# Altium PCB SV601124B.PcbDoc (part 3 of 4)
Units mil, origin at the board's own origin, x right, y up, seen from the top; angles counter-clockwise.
Board outline 3733 x 2734 mil, 4 copper layers (Top Layer, Mid-Layer 1, Mid-Layer 2, Bottom Layer), stack 60.2 mil thick; 246 components, 169 nets, 780 pads, 426 vias.
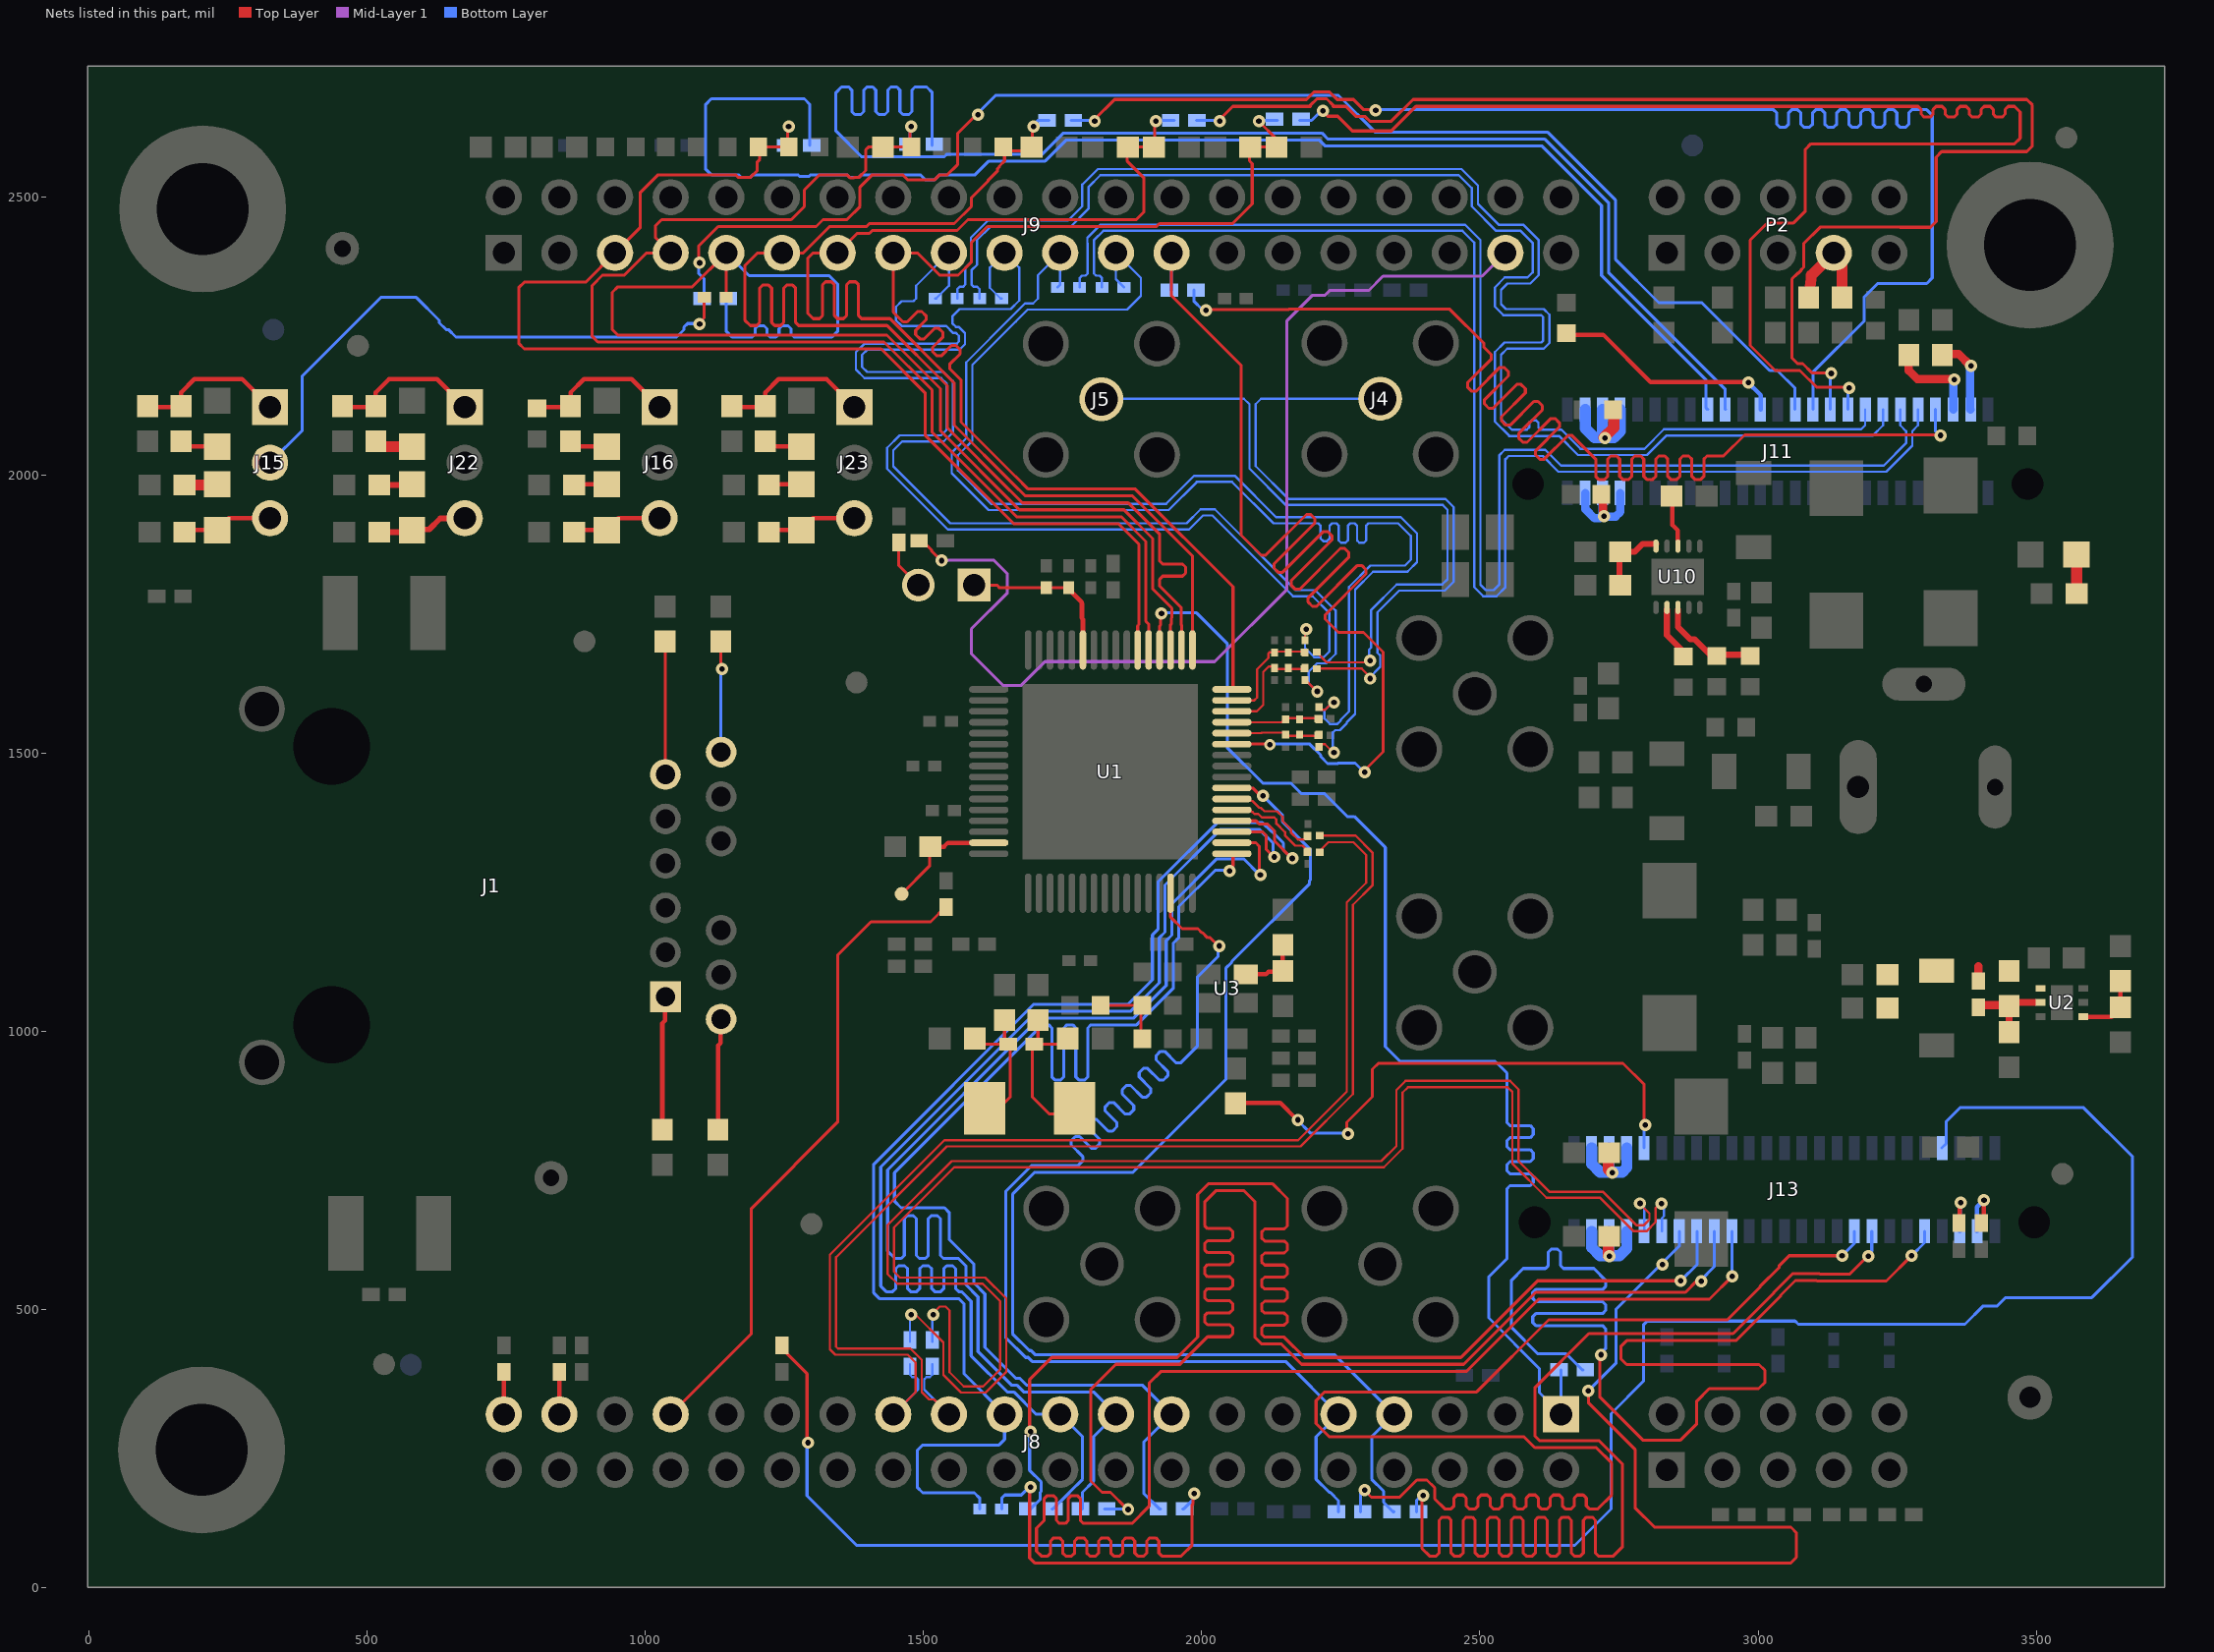
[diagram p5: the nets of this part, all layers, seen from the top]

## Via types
v1: diameter 22, hole 10, Top Layer to Bottom Layer, 385 vias
v2: diameter 19.68, hole 7.87, Top Layer to Bottom Layer, 40 vias
v3: diameter 20, hole 10, Top Layer to Bottom Layer, 1 vias

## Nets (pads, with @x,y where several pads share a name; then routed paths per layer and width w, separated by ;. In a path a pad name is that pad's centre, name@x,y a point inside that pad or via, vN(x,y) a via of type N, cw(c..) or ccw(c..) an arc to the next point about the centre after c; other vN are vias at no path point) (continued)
NetC5_1: C5.1 J4.1 | length 1252.1
  Top Layer w4.1: C5.1@2206,1652 2287.64,1652 2301,1638.64 v1@2301,1635
  Bottom Layer w4.1: v1@2301,1635 2321.05,1655.05 2321.05,1675.31 2316,1680.36 2316,1753 2355,1792 2437,1792 2453,1808 2453,1942 2438,1957 2156,1957 2097.1,2015.9 2097.1,2127.1 2107,2137 J4.1@2321,2137
  other v1: 2303,1634
NetC6_1: C6.1 J5.1 | length 1252.6
  Top Layer w4.1: C6.1@2206,1682 2224.9,1663.1 2297.1,1663.1 v1@2301,1667
  Bottom Layer w4.1: J5.1@1821,2137 2076,2137 2086,2127 2086,2011.3 2151.4,1945.9 2433.4,1945.9 2441.9,1937.4 2441.9,1812.6 2432.4,1803.1 2350.4,1803.1 2304.9,1757.6 2304.9,1689.96 2301,1686.06 v1@2301,1667
  other v1: 2303,1666
NetC7_1: C7.1 J1.7 | length 202.1
  Top Layer w8: C7.1@1131,822 1131,974.5 1136,979.5 J1.7@1136,1022
NetC8_1: C8.1 J1.1 | length 242.1
  Top Layer w8: C8.1@1031,822 1031,1014.5 1036,1019.5 J1.1@1036,1062
NetC9_1: C9.1 J1.6 | length 240
  Top Layer w5.4: J1.6@1036,1462 C9.1@1036,1702
NetC10_1: C10.1 J1.12 | length 200
  Top Layer w5.4: v1@1136,1652 C10.1@1136,1702
  Bottom Layer w5.4: J1.12@1136,1502 v1@1136,1652
  other v1: 1138,1651
NetC13_1: C13.1 C133.1 R86.2 R89.1 R90.2 U2.1 | length 30
  Top Layer w15: C13.1@3396,1087 3396,1117
NetC13_2: C13.2 R86.1 R87.2 U2.2 | length 154.1
  Top Layer w12: R87.2@3451,997 3451,1047 3456,1052 3498,1052
  Top Layer w15: C13.2@3396,1047 R86.1@3451,1047
NetC104_2: C104.2 U10.7 | length 93.5
  Top Layer w11: U10.7@2836.31,1757.94 2836.31,1727.94 2836,1727.63 2836,1712 2866,1682 C104.2@2866,1677
NetC273_1: C273.1 R652.1 R653.1 XTAL1.2 | length 272.7
  Top Layer w5.4: C273.1@1591,987 1601,977 R652.1@1656,977 ; XTAL1.2@1609,852 1626,852 1656,882 R652.1@1656,977 ; R653.1@1646,1022 1646,987 R652.1@1656,977
NetC274_1: C274.1 R652.2 R654.1 XTAL1.1 | length 300.7
  Top Layer w5.4: R654.1@1706,1022 1706,987 R652.2@1696,977 ; C274.1@1761,987 1751,977 R652.2@1696,977 ; XTAL1.1@1771,852 1726,852 1696,882 R652.2@1696,977
NetJ8_33: J8.33 R38.1 | length 1182.7
  Top Layer w5.4: J8.33@1046,312 1191,457 1191,682 1346,837 1346,1137 1406,1197 1513,1197 1541,1225 R38.1@1541,1227
NetJ8_37: J8.37 R77.2 | length 80
  Top Layer w8: J8.37@846,312 R77.2@846,392
NetJ8_39: J8.39 R73.2 | length 80
  Top Layer w8: J8.39@746,312 R73.2@746,392
NetJ11_3: J11.3 R62.1 | length 137.9
  Top Layer w15: R62.1@3331,2217 3361,2217 v1@3381,2197
  Bottom Layer w15: v1@3381,2197 3381,2118.13 J11.3@3381.55,2117.58
  other v1: 3383,2196
NetJ11_5: J11.5 R52.1 | length 170.2
  Top Layer w15: R52.1@3271,2217 3271,2187.5 3286.05,2172.45 v1@3350.55,2172.45
  Bottom Layer w15: J11.5@3350.55,2117.58 v1@3350.55,2172.45
  other v1: 3352.55,2171.45
NetJ11_27: J11.27 R63.1 | length 419.4
  Top Layer w8: R63.1@2656,2252 2721.72,2252 2806.72,2167 v1@2981,2167
  Bottom Layer w8: v1@2981,2167 3004.55,2143.45 J11.27@3004.55,2117.58
  other v1: 2983,2166
NetJ11_43: J11.43 J11.45 J11.47 R33.1 | length 256.8
  Top Layer w20: v1@2723,2067 2741,2085 R33.1@2741,2117
  Bottom Layer w20: J11.47@2689.55,2117.58 2689.55,2083.45 2706,2067 v1@2723,2067 ; J11.45@2720.55,2117.58 2720.55,2069.45 v1@2723,2067 ; J11.43@2752.55,2117.58 2752.55,2078.55 2741,2067 v1@2723,2067
  other v1: 2725,2066
NetJ11_44: J11.44 J11.46 J11.48 R23.2 | length 220.1
  Top Layer w15: v1@2721,1927 R23.2@2721,1967
  Bottom Layer w15: J11.48@2689.55,1967.58 2689.55,1938.45 2706,1922 2716,1922 v1@2721,1927 ; J11.46@2720.55,1967.58 2720.55,1927.45 v1@2721,1927 ; J11.44@2752.55,1967.58 2752.55,1933.55 2744.1,1925.1 2722.9,1925.1 v1@2721,1927
  other v1: 2723,1926
NetJ12_2: J12.2 R661.2 | length 94.5
  Top Layer w5.4: R661.2@1456,1882 1456,1837 J12.2@1491,1802
NetJ13_4: J13.4 R67.2 | length 108.5
  Top Layer w8: R67.2@3401,652 3406,657 v1(3406,697)
  Bottom Layer w8: J13.4@3393.36,640.8 3393.36,684.36 v1(3406,697)
NetJ13_6: J13.6 R69.2 | length 94.5
  Top Layer w8: R69.2@3361,652 3362.36,653.36 v1@3362.36,693.36
  Bottom Layer w8: J13.6@3362.36,640.8 v1@3362.36,693.36
  other v1: 3364.36,692.36
NetJ13_7: J13.7 R82.1 | length 3695.2
  Top Layer w5.4: R82.1@1246,432 1246,430 1291,385 v1@1291,262
  Bottom Layer w5.4: v1@1291,262 1291,165.62 1380.02,76.6 2670.68,76.6 2735.83,141.75 2735.83,313.04 2794.04,371.25 2794.04,472.5 2801.14,479.6 3066.58,479.6 3072.28,473.9 3371.74,473.9 3404.54,506.7 3430.14,506.7 3445.14,521.7 3599.78,521.7 3673,594.92 3673,775 3585,863 3363,863 3338,838 3338,798.44 J13.7@3330.36,790.8
  other v1: 1293,261
NetJ13_41: J13.41 R105.1 | length 979.2
  Top Layer w5.4: v1@2261,817 2261,836.7 2307,882.7 2307,932 2317.7,942.7 2757.3,942.7 2795.36,904.64 v1@2795.36,832.64
  Top Layer w8: R105.1@2061,872 2141,872 v1@2171,842
  Bottom Layer w5.4: v1@2171,842 2196,817 v1@2261,817 ; J13.41@2795.36,790.8 v1@2795.36,832.64
  other v1: 2263,816 2797.36,831.64 2173,841
NetJ13_43: J13.43 J13.45 J13.47 R58.1 | length 217.4
  Top Layer w20: R58.1@2731,782 2731,752 v1@2736,747
  Bottom Layer w20: J13.47@2701.36,790.8 2701.36,761.64 2716,747 2728.72,747 v1@2732.36,750.64 ; J13.45@2732.36,790.8 v1@2732.36,750.64 ; J13.43@2764.36,790.8 2764.36,755.36 2756,747 2736,747 v1@2732.36,750.64
  other v1: 2738,746
NetJ13_44: J13.44 J13.46 J13.48 R56.2 | length 213.6
  Top Layer w20: v1@2731,597 R56.2@2731,632
  Bottom Layer w20: J13.48@2701.36,640.8 2701.36,611.64 2716,597 v1@2731,597 ; J13.46@2732.36,640.8 2732.36,598.36 v1@2731,597 ; J13.44@2764.36,640.8 2764.36,610.36 2751,597 v1@2731,597
  other v1: 2733,596
NetJ15_1: J15.1 R25.2 R211.1 | length 276.7
  Top Layer w8: R25.2@106,2122 166,2122 166,2148 190,2172 276,2172 J15.1@326,2122
NetJ15_3: J15.3 LD21.2 R24.1 | length 165.4
  Top Layer w8: R24.1@171,1897 175.02,1901.02 231,1901.02 251.98,1922 J15.3@326,1922
NetJ16_1: J16.1 R16.2 R42.1 | length 276.7
  Top Layer w8: R16.2@806,2122 866,2122 866,2148 890,2172 976,2172 J16.1@1026,2122
NetJ16_3: J16.3 LD2.2 R15.1 | length 165.4
  Top Layer w8: R15.1@871,1897 875.02,1901.02 931,1901.02 951.98,1922 J16.3@1026,1922
NetJ22_1: J22.1 R18.2 R209.1 | length 276.7
  Top Layer w8: R18.2@456,2122 516,2122 516,2148 540,2172 626,2172 J22.1@676,2122
NetJ22_3: J22.3 LD20.2 R17.1 | length 156.8
  Top Layer w10: R17.1@522.5,1897 LD20.2@577.34,1897 ; LD20.2@582.34,1902 612,1902 632,1922 J22.3@676,1922
NetJ23_1: J23.1 R21.2 R210.1 | length 276.7
  Top Layer w8: R21.2@1156,2122 1216,2122 1216,2148 1240,2172 1326,2172 J23.1@1376,2122
NetJ23_3: J23.3 LD19.2 R19.1 | length 165.4
  Top Layer w8: R19.1@1221,1897 1225.02,1901.02 1281,1901.02 1301.98,1922 J23.3@1376,1922
NetLD2_1: LD2.1 R45.2 | length 60.4
  Top Layer w8: R45.2@871,1982 871.98,1982.98 LD2.1@931,1982.98
NetLD3_1: LD3.1 R42.2 | length 54
  Top Layer w8: R42.2@876.98,2051.02 LD3.1@931,2051.02
NetLD17_1: LD17.1 R170.1 | length 69.8
  Top Layer w20: R170.1@3572.5,1787 LD17.1@3572.5,1856.84
NetLD19_1: LD19.1 R212.2 | length 59
  Top Layer w8: R212.2@1221.98,1982.98 LD19.1@1281,1982.98
NetLD20_1: LD20.1 R213.2 | length 57.2
  Top Layer w10: R213.2@522.5,1982 LD20.1@579.66,1982
NetLD21_1: LD21.1 R214.1 | length 57.2
  Top Layer w20: R214.1@172.5,1982 LD21.1@229.66,1982
NetLD22_1: LD22.1 R209.2 | length 55.2
  Top Layer w20: R209.2@525.84,2050.66 LD22.1@581,2050.66
NetLD23_1: LD23.1 R210.2 | length 54
  Top Layer w8: R210.2@1226.98,2051.02 LD23.1@1281,2051.02
NetLD24_1: LD24.1 R211.2 | length 69.5
  Top Layer w8: R211.2@166,2062 176.98,2051.02 LD24.1@231,2051.02
NetP2_7: P2.7 R95.2 R96.2 | length 187.1
  Top Layer w20: R96.2@3091,2317 3096,2359 P2.7@3136,2399 3151,2384 R95.2@3151,2317
NetR9_1: R9.1 R20.2 U10.5 | length 131.5
  Top Layer w11: R20.2@2751,1802 2751,1862 2778.5,1862 2792.56,1876.06 U10.5@2816.63,1876.06
NetR43_2: R43.2 U10.3 | length 90.1
  Top Layer w8: R43.2@2846,1962 2846,1910.26 2856,1900.26 U10.3@2856,1876.06
NetR97_1: R97.1 R648.2 U3.1 | length 118.4
  Top Layer w8: U3.1@2079.5,1102.51 2115.51,1102.51 2120,1107 2146,1107 R97.1@2146,1157
NetR98_2: R98.2 R650.1 R660.2 | length 130
  Top Layer w5.4: R660.2@1821,1047 1891,1047 R98.2@1891,987
NetR133_2: R133.2 R177.2 U2.4 | length 118.9
  Top Layer w8: U2.4@3588.53,1026.4 3635.4,1026.4 3651,1042 R133.2@3651,1092
NetR640_1: R640.1 R641.2 U10.8 | length 181.5
  Top Layer w11: U10.8@2856,1757.94 2856,1727.23 2878.73,1704.5 2886.18,1704.5 2913.68,1677 2926,1677 R640.1@2986,1677
RBIAS: R645.2 TP1.1 U1.15 | length 213.1
  Top Layer w5.4: TP1.1@1461,1247 1511,1297 R645.2@1511,1332
  Top Layer w8: R645.2@1511,1332 1537,1332 1544.08,1339.08 U1.15@1615.46,1339.08
RESET_N: C318.2 J12.1 R35.1 U1.59 | length 323.8
  Top Layer w5.4: J12.1@1591,1802 1632.18,1802 1637.18,1797 1721,1797 C318.2@1761,1797 ; 1784.57,1771.43 1786.8,1769.2 1786.8,1740.78
  Top Layer w8: C318.2@1761,1797 1761,1795 1784.57,1771.43 1784.57,1743.01 1786.8,1740.78 U1.59@1786.8,1687.54
RESET_N_H: J9.37 R50.1 | length 1938.8
  Top Layer w5.4: R50.1@1496,1882 1498,1882 1514.86,1865.14 1514.86,1863.14 v1@1531,1847
  Mid-Layer 1 w5.4: v1@1531,1847 1626,1847 1651,1822 1651,1787.87 1586.5,1723.37 1586.5,1678.38 1642.89,1621.99 1675.99,1621.99 1718.5,1664.5 2023.5,1664.5 2153.5,1794.5 2153.5,2277.08 2198.92,2322.5 2221.21,2322.5 2230.31,2331.6 2300.6,2331.6 2326,2357 2504,2357 J9.37@2546,2399
  other v1: 1533,1846
RX_CLK: J9.25 R60.1 U1.43 | length 2320.5
  Top Layer w5.4: J9.25@1946,2399 1946,2322 2071,2197 2071,1892 2107.42,1855.58 2115.04,1855.58 2188.42,1928.96 2196.04,1928.96 2203.7,1921.3 2203.7,1913.68 2130.32,1840.3 2130.32,1832.68 2137.98,1825.02 2145.6,1825.02 2218.98,1898.4 2226.6,1898.4 2234.26,1890.74 2234.26,1883.12 2160.88,1809.74 2160.88,1802.12 2168.54,1794.46 2176.16,1794.46 2249.54,1867.84 2257.16,1867.84 2264.82,1860.18 2264.82,1852.56 2191.44,1779.18 2191.44,1771.56 2199.1,1763.9 2206.72,1763.9 2280.1,1837.28 2287.72,1837.28 2295.38,1829.62 2295.38,1822 2222,1748.62 2222,1741 2246,1717 2291,1717 2326.4,1681.6 2326.4,1502.4 v1@2291,1467 ; U1.43@2056.54,1516.2 v3@2121,1516.2
  Bottom Layer w5.4: R60.1@1946,2332 J9.25@1946,2399 ; v3@2121,1516.2 2194.53,1516.2 2214.15,1496.58 2214.15,1493.85 2226.64,1481.36 2244.58,1481.36 2245.22,1482 2276,1482 v1@2291,1467
  other v1: 2293,1466
  other v3: 2123,1515.2
RX_CLK_EMB: J11.7 R60.2 | length 2549.2
  Top Layer w5.4: v1@2006,2297 2024.68,2297 2024.98,2297.3 2156.3,2297.3 2156.7,2297.7 2446.15,2297.7 2507.51,2236.33 2507.51,2229.23 2520.73,2216.01 2520.73,2208.39 2477.98,2165.64 2477.98,2158.02 2485.64,2150.36 2493.26,2150.36 2536.01,2193.11 2543.63,2193.11 2551.29,2185.45 2551.29,2177.83 2508.54,2135.08 2508.54,2127.46 2516.2,2119.8 2523.82,2119.8 2566.57,2162.55 2574.19,2162.55 2581.85,2154.89 2581.85,2147.27 2539.1,2104.52 2539.1,2096.9 2546.76,2089.24 2554.38,2089.24 2597.13,2131.99 2604.75,2131.99 2612.41,2124.33 2612.41,2116.71 2569.66,2073.96 2569.66,2066.34 2577.32,2058.68 2584.94,2058.68 2627.69,2101.43 2635.31,2101.43 2642.97,2093.77 2642.97,2086.15 2600.22,2043.4 2600.22,2035.78 2607.88,2028.12 2615.5,2028.12 2658.25,2070.87 2665.87,2070.87 2708.24,2028.5 2708.24,1997.4 2713.64,1992 2724.44,1992 2729.84,1997.4 2729.84,2028.5 2735.24,2033.9 2746.04,2033.9 2751.44,2028.5 2751.44,1997.4 2756.84,1992 2767.64,1992 2773.04,1997.4 2773.04,2028.5 2778.44,2033.9 2789.24,2033.9 2794.64,2028.5 2794.64,1997.4 2800.04,1992 2810.84,1992 2816.24,1997.4 2816.24,2028.5 2821.64,2033.9 2832.44,2033.9 2837.84,2028.5 2837.84,1997.4 2843.24,1992 2854.04,1992 2859.44,1997.4 2859.44,2028.5 2864.84,2033.9 2875.64,2033.9 2881.04,2028.5 2881.04,1997.4 2886.44,1992 2897.24,1992 2902.64,1997.4 2902.64,2028.5 2908.04,2033.9 2937.9,2033.9 2976,2072 v1@3326,2072
  Bottom Layer w5.4: R60.2@1986,2332 1986,2312.3 2001.3,2297 v1@2006,2297 ; J11.7@3318.55,2117.58 3318.55,2079.45 v1@3326,2072
  other v1: 3328,2071 2008,2296
RX_DV: J9.7 R7.1 R8.2 R53.2 U1.53 | length 2336
  Top Layer w5.4: v1@1476,2627 1476,2589 1426,2589 1401.3,2589 1396.7,2584.4 1396.7,2546.95 1384.58,2534.83 1376.49,2534.83 1375.6,2533.94 1367.96,2533.94 1362.67,2539.23 1313.46,2539.23 1286.23,2512 1286.23,2482.33 1262.67,2458.77 1029.77,2458.77 1018.96,2447.96 1018.96,2426.04 J9.7@1046,2399 1002.9,2399 962.67,2358.77 923.31,2358.77 905,2340.46 905,2248.9 915,2238.9 1429.26,2238.9 1515.6,2152.56 1515.6,2076.86 1667.56,1924.9 1855.56,1924.9 1899.94,1880.52 1899.94,1736.94 1904.88,1732 U1.53@1904.88,1687.54
  Bottom Layer w5.4: R53.2@1476,2592 v1@1476,2627
  other v1: 1478,2626
RX_DV_EMB: J11.31 R53.1 | length 2538.8
  Bottom Layer w5.4: R53.1@1516,2592 1516,2687 1506,2697 1484.88,2697 1479.48,2691.6 1479.48,2653.1 1474.08,2647.7 1463.28,2647.7 1457.88,2653.1 1457.88,2691.6 1452.48,2697 1441.68,2697 1436.28,2691.6 1436.28,2653.1 1430.88,2647.7 1420.08,2647.7 1414.68,2653.1 1414.68,2691.6 1409.28,2697 1398.48,2697 1393.08,2691.6 1393.08,2653.1 1387.68,2647.7 1376.88,2647.7 1371.48,2653.1 1371.48,2691.6 1366.08,2697 1353,2697 1343,2687 1343,2617.81 1389.02,2571.79 1537.79,2571.79 1542.43,2576.43 1713.91,2576.43 1751.88,2614.4 2216.22,2614.4 2227.42,2603.2 2617.14,2603.2 2731.2,2489.14 2731.2,2363.62 2941,2153.82 2941,2118.13 J11.31@2941.55,2117.58
RX_ER: J9.5 R5.1 R6.2 R71.2 U1.54 | length 2320.4
  Top Layer w5.4: v1@1256,2627 1256,2589 1206,2589 1206,2567 1201.7,2562.7 1201.7,2546.95 1189.58,2534.83 1167.07,2534.83 1162.67,2539.23 1023.23,2539.23 991,2507 991,2444 J9.5@946,2399 893.37,2346.37 783,2346.37 773,2336.37 773,2236.5 783,2226.5 1424.12,2226.5 1503.2,2147.42 1503.2,2071.72 1662.42,1912.5 1850.42,1912.5 1887.54,1875.38 1887.54,1731.08 1885.2,1728.74 U1.54@1885.2,1687.54
  Bottom Layer w5.4: R71.2@1256,2592 v1@1256,2627
  other v1: 1258,2626
RX_ER_EMB: J11.33 R71.1 | length 2537.3
  Bottom Layer w5.4: R71.1@1296,2592 1296,2666 1286,2676 1119,2676 1109,2666 1109,2549.23 1119,2539.23 1168.02,2539.23 1172.42,2534.83 1189.58,2534.83 1193.98,2539.23 1274.49,2539.23 1277.42,2536.3 1294.58,2536.3 1297.51,2539.23 1363.02,2539.23 1367.42,2534.83 1384.58,2534.83 1388.98,2539.23 1494.49,2539.23 1503.33,2530.39 1520.49,2530.39 1529.33,2539.23 1593.15,2539.23 1617.95,2564.03 1719.05,2564.03 1757.02,2602 2211.08,2602 2222.28,2590.8 2612,2590.8 2718.8,2484 2718.8,2358.48 2906,2171.28 2906,2121.13 J11.33@2909.55,2117.58
RXD0: C1.2 R32.1 R34.2 R65.1 U1.44 | length 157.1
  Top Layer w4.1: U1.44@2056.54,1535.88 2107.32,1535.88 2108.18,1536.74 2145.56,1536.74 2151,1531.3 2176,1531.3 C1.2@2211,1531.3
RXD0_EMB: J11.9 R48.2 | length 2546
  Bottom Layer w4.1: R48.2@1821,2337 1821,2353.85 1816.9,2357.95 1810.65,2357.95 1806.55,2362.05 1806.55,2382.47 1806.42,2382.6 1806.42,2421.72 1823.28,2438.58 2468.72,2438.58 2489.9,2417.4 2489.9,1798.31 2506.21,1782 2529.64,1782 2545.95,1798.31 2545.95,2028 2551.85,2033.9 2613.12,2033.9 2641.17,2005.85 3230.55,2005.85 3277.1,2052.4 3277.1,2078.59 3287.55,2089.04 J11.9@3287.55,2117.58
RXD0_H: J9.23 R48.1 R65.2 | length 2161.6
  Top Layer w4.1: R65.2@2211,1512.7 2214.55,1516.25 2221.81,1516.25 v1@2236,1502.06
  Bottom Layer w4.1: R48.1@1861,2337 1846,2352 J9.23@1846,2399 1891,2354 1891,2322 1866.05,2297.05 1687.45,2297.05 1666.15,2275.75 1588.1,2197.71 1588.1,2061.41 1562.1,2035.41 1562.1,2007.9 1621.9,1948.1 1936.4,1948.1 1986.8,1998.5 2059.5,1998.5 2134,1924 2358,1924 2387.1,1894.9 2387.1,1843.08 2370.86,1826.84 2370.01,1826 2308,1826 2276,1794 2276,1570.36 2260.95,1555.31 2260.95,1553.6 2248.8,1541.45 2240.1,1541.45 2236,1537.35 v1@2236,1502.06
  other v1: 2238,1501.06
RXD1: C2.2 R30.1 R31.2 R64.1 U1.45 | length 157.7
  Top Layer w4.1: U1.45@2056.54,1555.56 2143.86,1555.56 2151,1562.7 2176,1562.7 2205.3,1562.7 2206,1562 C2.2@2211,1562
RXD1_EMB: J11.11 R70.1 | length 2547.8
  Bottom Layer w4.1: R70.1@1781,2337 1781,2353.85 1785.1,2357.95 1791.35,2357.95 1795.45,2362.05 1795.45,2377.87 1795.32,2378 1795.32,2416.28 1794.89,2416.7 1794.89,2425.9 1818.68,2449.68 2473.32,2449.68 2501,2422 2501,1802.91 2510.81,1793.1 2525.04,1793.1 2534.85,1802.91 2534.85,2035 2544.85,2045 2617.72,2045 2645.77,2016.95 3225.95,2016.95 3266,2057 3266,2078.59 3255.55,2089.04 J11.11@3255.55,2117.58
RXD1_H: J9.21 R64.2 R70.2 | length 2160.5
  Top Layer w4.1: R64.2@2211,1581.3 2214.55,1577.75 2221.81,1577.75 v1@2236,1591.94
  Bottom Layer w4.1: R70.2@1741,2337 1746,2342 J9.21@1746,2399 1706,2359 1706,2317 1697.15,2308.15 1682.85,2308.15 1661.55,2286.85 1577,2202.31 1577,2066.01 1551,2040.01 1551,2003.3 1617.3,1937 1941,1937 1991.4,1987.4 2054.9,1987.4 2129.4,1912.9 2209.64,1912.9 2213.74,1908.8 2213.74,1885.8 2218.54,1881 2225.34,1881 2230.14,1885.8 2230.14,1908.8 2234.24,1912.9 2242.44,1912.9 2246.54,1908.8 2246.54,1882.1 2250.64,1878 2258.84,1878 2262.94,1882.1 2262.94,1908.8 2267.04,1912.9 2275.24,1912.9 2279.34,1908.8 2279.34,1882.1 2283.44,1878 2291.64,1878 2295.74,1882.1 2295.74,1908.8 2299.84,1912.9 2353.4,1912.9 2376,1890.3 2376,1847.68 2365.42,1837.1 2303.4,1837.1 2264.9,1798.6 2264.9,1574.96 2249.85,1559.91 2249.85,1558.2 2244.2,1552.55 2230.45,1552.55 2221,1562 2221,1576.94 v1@2236,1591.94
  other v1: 2238,1590.94
RXD2: C5.2 R28.1 R29.2 R61.1 U1.46 | length 199.3
  Top Layer w4.1: U1.46@2056.54,1575.24 2099.24,1575.24 2110.95,1586.95 2110.95,1645.95 2120.9,1655.9 2126.4,1655.9 2131,1651.3 2156,1651.3 C5.2@2186,1651.3
RXD2_EMB: J11.13 R54.2 | length 2554.5
  Bottom Layer w4.1: R54.2@1601,2317 1601,2333.85 1596.9,2337.95 1590.65,2337.95 1586.55,2342.05 1586.55,2367.55 1596.68,2377.68 1596.68,2421.98 1620.6,2445.9 1764.58,2445.9 1796.68,2478 1796.68,2516.98 1818.28,2538.58 2462.4,2538.58 2485.58,2515.4 2485.58,2482.42 2529.42,2438.58 2573.32,2438.58 2594.9,2417 2594.9,2363.9 2586,2355 2545,2355 2527,2337 2527,2302.3 2542.4,2286.9 2610.4,2286.9 2613.9,2283.4 2613.9,2241.6 2610.4,2238.1 2544.5,2238.1 2527,2220.6 2527,2095.99 2552.99,2070 2642.3,2070 2676.45,2035.85 2800.55,2035.85 2835.6,2070.9 3206.41,2070.9 3224.55,2089.04 J11.13@3224.55,2117.58
RXD2_H: J9.19 R54.1 R61.2 | length 2154.9
  Top Layer w4.1: R61.2@2186,1632.7 2186,1632 v1@2206,1612
  Bottom Layer w4.1: R54.1@1641,2317 1639,2317 1619.42,2336.58 1619.42,2372.42 J9.19@1646,2399 1672.58,2372.42 1672.58,2313.58 1656.95,2297.95 1565.21,2297.95 1552.1,2284.84 1552.1,2272.4 1558.5,2266 1563.6,2266 1575,2254.6 1575,2235 1564.9,2224.9 1398.99,2224.9 1390.1,2216.01 1390.1,2193.9 1399,2185 1536.6,2185 1553.1,2168.5 1553.1,2076.5 1536.6,2060 1462,2060 1446.1,2044.1 1446.1,2015.6 1548.6,1913.1 1973.04,1913.1 1998.09,1938.15 2023.91,1938.15 2169.06,1793 2204,1793 2240.93,1756.07 2240.93,1678.58 2223.8,1661.45 2207.45,1661.45 2192.52,1646.52 2192.52,1625.48 v1@2206,1612
  other v1: 2208,1611
RXD3: C6.2 R26.1 R27.2 R51.1 U1.47 | length 199.6
  Top Layer w4.1: U1.47@2056.54,1594.92 2094.75,1594.92 2099.85,1600.02 2099.85,1650.85 2120,1671 2120,1679 2121.98,1680.98 R26.1@2131,1680.98 ; R26.1@2131,1682.7 C6.2@2186,1682.7
RXD3_EMB: J11.15 R47.2 | length 2560.5
  Bottom Layer w4.1: R47.2@1561,2317 1561,2333.85 1565.1,2337.95 1571.35,2337.95 1575.45,2342.05 1575.45,2372.15 1585.58,2382.28 1585.58,2426.58 1616,2457 1759.98,2457 1785.58,2482.6 1785.58,2521.58 1813.68,2549.68 2467,2549.68 2496.68,2520 2496.68,2487.02 2534.02,2449.68 2577.92,2449.68 2606,2421.6 2606,2359.3 2590.6,2343.9 2549.6,2343.9 2538.1,2332.4 2538.1,2306.9 2547,2298 2615,2298 2625,2288 2625,2237 2615,2227 2549.1,2227 2538.1,2216 2538.1,2100.59 2557.59,2081.1 2584.65,2081.1 2588.75,2085.2 2588.75,2093.9 2592.85,2098 2601.05,2098 2605.15,2093.9 2605.15,2085.2 2609.25,2081.1 2646.9,2081.1 2681.05,2046.95 2795.95,2046.95 2831,2082 3185.51,2082 3192.55,2089.04 J11.15@3192.55,2117.58
RXD3_H: J9.17 R47.1 R51.2 | length 2143.4
  Top Layer w4.1: R51.2@2186,1701.3 v1@2186,1723.8
  Bottom Layer w4.1: R47.1@1521,2317 1523,2317 1546,2340 J9.17@1546,2399 1487,2340 1487,2317 1482,2312 1461,2312 1451,2302 1451,2277.8 1461,2267.8 1541,2267.8 1553.9,2254.9 1559,2254.9 1563.9,2250 1563.9,2239.6 1560.3,2236 1394.4,2236 1392,2233.6 1379,2220.61 1379,2189.3 1394.4,2173.9 1532,2173.9 1542,2163.9 1542,2081.1 1532,2071.1 1457.4,2071.1 1435,2048.7 1435,2011 1544,1902 1977.64,1902 2002.69,1927.05 2019.31,1927.05 2164.46,1781.9 2199.4,1781.9 2229.83,1751.47 2229.83,1683.18 2219.2,1672.55 2202.45,1672.55 2186,1689 v1@2186,1723.8
  other v1: 2188,1722.8
RXD4: J9.15 R74.2 R290.1 R292.2 U1.48 | length 2322.8
  Top Layer w5.4: U1.48@2056.54,1614.6 2056.54,1799 1881.04,1974.5 1688.5,1974.5 1666.24,1996.76 1665.86,1996.76 1567.8,2094.82 1567.8,2170.52 1547.32,2191 1547.32,2198.62 1566.04,2217.34 1566.04,2224.96 1558.38,2232.62 1550.76,2232.62 1532.04,2213.9 1524.42,2213.9 1516.76,2221.56 1516.76,2229.18 1535.48,2247.9 1535.48,2255.52 1527.82,2263.18 1520.2,2263.18 1501.48,2244.46 1493.86,2244.46 1486.2,2252.12 1486.2,2259.74 1504.92,2278.46 1504.92,2286.08 1497.26,2293.74 1489.64,2293.74 1470.92,2275.02 1463.3,2275.02 1446,2292.32 J9.15@1446,2399 1489.1,2399 1529.33,2358.77 1562.67,2358.77 1586.23,2382.33 1586.23,2417.43 1615.17,2446.37 1918.93,2446.37 1924.19,2451.63 2055.63,2451.63 2091,2487 2091,2559.3 2086,2564.3 2086,2589 2136,2589 2136,2602 v1@2101,2637
  Bottom Layer w5.4: v1@2101,2637 R74.2@2136,2637
  other v1: 2103,2636
RXD4_EMB: J11.17 R74.1 | length 2552.4
  Top Layer w5.4: v1@2216,2655.3 2226.7,2644.6 2244.58,2644.6 2271.09,2618.09 2341.03,2618.09 2385.14,2662.2 3287.6,2662.2 3293,2656.8 3293,2648.4 3298.4,2643 3309.2,2643 3314.6,2648.4 3314.6,2656.8 3320,2662.2 3330.8,2662.2 3336.2,2656.8 3336.2,2648.4 3341.6,2643 3352.4,2643 3357.8,2648.4 3357.8,2656.8 3363.2,2662.2 3374,2662.2 3379.4,2656.8 3379.4,2648.4 3384.8,2643 3395.6,2643 3401,2648.4 3401,2656.8 3406.4,2662.2 3417.2,2662.2 3422.6,2656.8 3422.6,2648.4 3428,2643 3438.8,2643 3444.2,2648.4 3444.2,2656.8 3449.6,2662.2 3461,2662.2 3471,2652.2 3471,2605 3461,2595 3095,2595 3085,2585 3085,2474 3063.8,2452.8 3016.8,2452.8 2986,2422 2986,2232.72 3031.02,2187.7 3075.13,2187.7 3105.28,2157.55 v1@3161.55,2157.55
  Bottom Layer w5.4: R74.1@2176,2637 2197.7,2637 v1@2216,2655.3 ; J11.17@3161.55,2117.58 v1@3161.55,2157.55
  other v1: 3163.55,2156.55 2218,2654.3
RXD5: J9.13 R12.1 R13.2 R72.2 U1.49 | length 2322.1
  Top Layer w5.4: v1@1916,2637 1916,2589 1866,2589 1866,2564.3 1896,2534.3 1896,2472 1882.77,2458.77 1580.21,2458.77 1560.67,2439.23 1408.31,2439.23 1403.05,2433.97 1380.97,2433.97 J9.13@1346,2399 1302,2399 1292,2389 1292,2290.8 1302,2280.8 1313.4,2280.8 1318.8,2286.2 1318.8,2341.6 1324.2,2347 1335,2347 1340.4,2341.6 1340.4,2286.2 1345.8,2280.8 1356.6,2280.8 1362,2286.2 1362,2341.6 1367.4,2347 1378.2,2347 1383.6,2341.6 1383.6,2286.2 1389,2280.8 1439.98,2280.8 1555.4,2165.38 1555.4,2089.68 1660.72,1984.36 1661.1,1984.36 1683.36,1962.1 1875.9,1962.1 1983.6,1854.4 U1.49@1983.6,1687.54
  Bottom Layer w5.4: v1@1916,2637 R72.2@1951,2637
  other v1: 1918,2636
RXD5_EMB: J11.19 R72.1 | length 2543
  Top Layer w5.4: v1@2031,2637 2056.2,2662.2 2195.3,2662.2 2195.3,2663.88 2207.42,2676 2224.58,2676 2236.7,2663.88 2236.7,2662.2 2259.68,2662.2 2277.98,2643.9 2294.12,2643.9 2302.42,2635.6 2341,2635.6 2380,2674.6 3483,2674.6 3493,2664.6 3493,2591 3483,2581 3330,2581 3320,2571 3320,2455 3310,2445 3255.34,2445 3255.14,2445.2 3111.4,2445.2 3082.2,2416 3082.2,2373.07 3077.24,2368.11 3077.11,2367.09 3072.2,2362.17 3071,2362.17 3061,2352.17 3061,2210.1 3071,2200.1 3080.27,2200.1 3096.92,2183.45 v1@3129.55,2183.45
  Bottom Layer w5.4: R72.1@1991,2637 v1@2031,2637 ; J11.19@3129.55,2117.58 v1@3129.55,2183.45
  other v1: 3131.55,2182.45 2033,2636
RXD6: J9.11 R10.1 R11.2 R59.1 U1.50 | length 2325
  Top Layer w5.4: v1@1696,2627 1696,2589 1689,2582 1653,2582 1646,2589 1646,2564.3 1636.7,2555 1636.7,2553.42 1633.46,2550.18 1633.46,2546.59 1616.7,2529.83 1616.7,2528.42 1586.23,2497.95 1586.23,2482.33 1555.53,2451.63 1403.17,2451.63 1397.91,2446.37 1331.61,2446.37 1284.24,2399 J9.11@1246,2399 1202.23,2399 1179,2375.77 1179,2278.4 1189,2268.4 1200.4,2268.4 1205.8,2273.8 1205.8,2335.6 1211.2,2341 1222,2341 1227.4,2335.6 1227.4,2273.8 1232.8,2268.4 1243.6,2268.4 1249,2273.8 1249,2335.6 1254.4,2341 1265.2,2341 1270.6,2335.6 1270.6,2273.8 1276,2268.4 1434.84,2268.4 1543,2160.24 1543,2084.54 1655.58,1971.96 1655.96,1971.96 1678.22,1949.7 1868.3,1949.7 1924.74,1893.26 1924.74,1845.15 1930.14,1839.75 1965.8,1839.75 1971.2,1834.35 1971.2,1823.55 1965.8,1818.15 1930.14,1818.15 1924.74,1812.75 1924.74,1800.08 1963.6,1761.22 1963.6,1730.1 1963.92,1729.78 U1.50@1963.92,1687.54
  Bottom Layer w5.4: v1@1696,2627 1706,2637 R59.1@1726,2637
  other v1: 1698,2626
RXD6_EMB: J11.21 R59.2 | length 2554.5
  Top Layer w5.4: v1@1806,2637 1843.6,2674.6 2188.48,2674.6 2202.28,2688.4 2229.72,2688.4 2243.52,2674.6 2273,2674.6 2291.3,2656.3 v1@2311,2656.3
  Bottom Layer w5.4: R59.2@1766,2637 v1@1806,2637 ; v1@2311,2656.3 3028.03,2656.3 3033.43,2650.9 3033.43,2630.4 3038.83,2625 3049.63,2625 3055.03,2630.4 3055.03,2650.9 3060.43,2656.3 3071.23,2656.3 3076.63,2650.9 3076.63,2630.4 3082.03,2625 3092.83,2625 3098.23,2630.4 3098.23,2650.9 3103.63,2656.3 3114.43,2656.3 3119.83,2650.9 3119.83,2630.4 3125.23,2625 3136.03,2625 3141.43,2630.4 3141.43,2650.9 3146.83,2656.3 3157.63,2656.3 3163.03,2650.9 3163.03,2630.4 3168.43,2625 3179.23,2625 3184.63,2630.4 3184.63,2650.9 3190.03,2656.3 3200.83,2656.3 3206.23,2650.9 3206.23,2630.4 3211.63,2625 3222.43,2625 3227.83,2630.4 3227.83,2650.9 3233.23,2656.3 3244.03,2656.3 3249.43,2650.9 3249.43,2630.4 3254.83,2625 3265.63,2625 3271.03,2630.4 3271.03,2650.9 3276.43,2656.3 3303,2656.3 3313,2646.3 3313,2354 3303,2344 3215,2344 3191,2320 3191,2276.9 3098.55,2184.45 J11.21@3098.55,2117.58
  other v1: 1808,2636 2313,2655.3
RXD7: J9.9 R37.1 R49.1 U1.51 | length 2397.7
  Top Layer w5.4: R37.1@1146,2319 J9.9@1146,2399 1085,2338 951,2338 941,2328 941,2261.3 951,2251.3 1434.4,2251.3 1530.6,2155.1 1530.6,2079.4 1672.7,1937.3 1860.7,1937.3 1912.34,1885.66 1912.34,1794.94 1946.7,1760.58 1946.7,1743.42 1946,1742.72 1946,1732.72 1944.24,1730.96 U1.51@1944.24,1687.54
  Bottom Layer w5.4: R49.1@1146,2317 1146,2257.7 1156,2247.7 1192.13,2247.7 1197.53,2253.1 1197.53,2262.6 1202.93,2268 1213.73,2268 1219.13,2262.6 1219.13,2253.1 1224.53,2247.7 1235.33,2247.7 1240.73,2253.1 1240.73,2262.6 1246.13,2268 1256.93,2268 1262.33,2262.6 1262.33,2253.1 1267.73,2247.7 1336,2247.7 1346,2257.7 1346,2343 1331,2358 1187,2358 J9.9@1146,2399
RXD7_EMB: J11.23 R49.2 | length 2560.1
  Top Layer w5.4: v1@1096,2382.1 1096,2411 1131.37,2446.37 1307.37,2446.37 1319.77,2458.77 1362.67,2458.77 1386.23,2482.33 1386.23,2517.23 1408.23,2539.23 1462.67,2539.23 1471.51,2530.39 1520.49,2530.39 1529.33,2539.23 1543.23,2539.23 1561.3,2557.3 1561.3,2613.3 v1@1596,2648
  Bottom Layer w5.4: v1@1096,2382.1 1096,2362.4 1106,2352.4 R49.2@1106,2317 ; v1@1596,2648 1630,2682 2246,2682 2312.4,2615.6 2622.28,2615.6 2743.6,2494.28 2743.6,2387.72 2821.72,2309.6 2898.95,2309.6 3020.85,2187.7 3034.58,2187.7 3066.55,2155.73 J11.23@3066.55,2117.58
  other v1: 1098,2381.1 1598,2647
RXD7_LED: J15.2 R37.2 | length 1046.4
  Top Layer w5.4: v1@1096,2272 1106,2282 R37.2@1106,2319
  Bottom Layer w5.4: J15.2@326,2022 384,2080 384,2178 525,2319 589,2319 630.3,2277.7 630.3,2273.42 642.42,2261.3 646.7,2261.3 660.3,2247.7 1056.7,2247.7 1069.96,2260.96 1069.96,2265.66 1076.3,2272 v1@1096,2272
  other v1: 1098,2271
TX_CLK: J8.9 R80.1 U1.30 | length 2331.4
  Top Layer w5.4: U1.30@1944.24,1246.46 1944.24,1205.4 1965.04,1184.6 1993.4,1184.6 2000.3,1177.7 2001.58,1177.7 2010.78,1168.5 2015.59,1168.5 v1@2029.53,1154.56
  Bottom Layer w5.4: v1@2029.53,1154.56 2029.53,1134.53 1992.23,1097.23 1992.23,973.23 1962.19,943.19 1954.57,943.19 1933.69,964.07 1926.07,964.07 1918.41,956.41 1918.41,948.79 1939.29,927.91 1939.29,920.29 1931.63,912.63 1924.01,912.63 1903.13,933.51 1895.51,933.51 1887.85,925.85 1887.85,918.23 1908.73,897.35 1908.73,889.73 1901.07,882.07 1893.45,882.07 1872.57,902.95 1864.95,902.95 1857.29,895.29 1857.29,887.67 1878.17,866.79 1878.17,859.17 1870.51,851.51 1862.89,851.51 1842.01,872.39 1834.39,872.39 1826.73,864.73 1826.73,857.11 1847.61,836.23 1847.61,828.61 1839.95,820.95 1832.33,820.95 1811.45,841.83 1803.83,841.83 1796.17,834.17 1796.17,826.55 1817.05,805.67 1817.05,798.05 1809.39,790.39 1801.77,790.39 1780.89,811.27 1773.27,811.27 1765.61,803.61 1765.61,795.99 1786.49,775.11 1786.49,767.49 1778.4,759.4 1695.01,759.4 1647.9,712.29 1647.9,450.1 1683.77,414.23 1688.37,414.23 1695.6,407 2151,407 J8.9@2246,312 2205.77,271.77 2205.77,195.33 2229.33,171.77 2231.23,171.77 2246,157 R80.1@2246,137
  other v1: 2031.53,1153.56
TX_CLK_EMB: J13.18 R80.2 | length 2542.6
  Top Layer w5.4: v1@2291,177 2304.94,163.06 2356.06,163.06 2387,194 2405,194 2419,180 2419,160 2437,142 2448.4,142 2453.8,147.4 2453.8,161.6 2459.2,167 2470,167 2475.4,161.6 2475.4,147.4 2480.8,142 2491.6,142 2497,147.4 2497,161.6 2502.4,167 2513.2,167 2518.6,161.6 2518.6,147.4 2524,142 2534.8,142 2540.2,147.4 2540.2,161.6 2545.6,167 2556.4,167 2561.8,161.6 2561.8,147.4 2567.2,142 2578,142 2583.4,147.4 2583.4,161.6 2588.8,167 2599.6,167 2605,161.6 2605,147.4 2610.4,142 2621.2,142 2626.6,147.4 2626.6,161.6 2632,167 2642.8,167 2648.2,161.6 2648.2,147.4 2653.6,142 2664.4,142 2669.8,147.4 2669.8,161.6 2675.2,167 2686,167 2691.4,161.6 2691.4,147.4 2696.8,142 2712,142 2737.23,167.23 2737.23,224.23 2709.23,252.23 2598.77,252.23 2579.23,271.77 2229.33,271.77 2205.77,295.33 2205.77,336.77 2221.23,352.23 2494.27,352.23 2623.74,481.7 2944.98,481.7 3003.3,540.02 3003.3,541.28 3038.32,576.3 3038.32,579.32 3056,597 v1(3151,597)
  Bottom Layer w5.4: R80.2@2286,137 2286,172 v1@2291,177 ; v1(3151,597) 3173.36,619.36 J13.18@3173.36,640.8
  other v1: 2293,176
TX_EN: J8.1 R79.1 U1.52 | length 2356.1
  Top Layer w5.4: U1.52@1924.56,1687.54 1924.56,1728.6 1926,1730.04 v1@1926,1752
  Bottom Layer w5.4: v1@1926,1752 1991,1752 2046,1697 2046,1510.01 2109.82,1446.19 2160.39,1446.19 2178.88,1427.7 2220.3,1427.7 2261.7,1386.3 2274.58,1386.3 2330.3,1330.58 2330.3,972.7 2356.7,946.3 2527.7,946.3 2548.66,925.34 2548.66,836.11 2554.06,830.71 2590.6,830.71 2596,825.31 2596,814.51 2590.6,809.11 2554.06,809.11 2548.66,803.71 2548.66,792.91 2554.06,787.51 2590.6,787.51 2596,782.11 2596,771.31 2590.6,765.91 2554.06,765.91 2548.66,760.51 2548.66,749.71 2554.06,744.31 2590.6,744.31 2596,738.91 2596,728.11 2590.6,722.71 2554.06,722.71 2548.66,717.31 2548.66,591.66 2516,559 2516,485.19 2607.05,394.14 2607.05,350.95 J8.1@2646,312 R79.1@2646,392
  other v1: 1928,1751
TX_EN_EMB: J13.10 R79.2 | length 2552.9
  Top Layer w5.4: v1@2716,420 2716,342.65 2792.86,265.8 2860.8,265.8 2889.8,294.8 2889.8,335.8 2912.2,358.2 2955.14,358.2 2955.34,358 3001,358 3012.19,369.19 3012.19,391 3001.89,401.3 2764,401.3 2754,411.3 2754,434.5 2764,444.5 2960.4,444.5 3040.5,524.6 3040.5,525.86 3067.14,552.5 3104.86,552.5 3105.86,551.5 3230.5,551.5 v1(3276,597)
  Bottom Layer w5.4: R79.2@2686,392 2684,392 2655,421 2604,421 2557,468 2557,553 2578,574 2617.9,574 2623.3,579.4 2623.3,603.6 2628.7,609 2639.5,609 2644.9,603.6 2644.9,579.4 2650.3,574 2705,574 2726,553 2726,541.6 2720.6,536.2 2600.53,536.2 2595.13,530.8 2595.13,520 2600.53,514.6 2720.6,514.6 2726,509.2 2726,498.4 2720.6,493 2600.53,493 2595.13,487.6 2595.13,476.8 2600.53,471.4 2720.6,471.4 2726,466 2726,430 v1@2716,420 ; v1(3276,597) 3299.36,620.36 J13.10@3299.36,640.8
  other v1: 2718,419
TX_ER: J8.7 R84.1 U1.39 | length 2342
  Top Layer w5.4: U1.39@2056.54,1437.48 2091.92,1437.48 2105.73,1423.67 v1(2110.41,1423.67)
  Bottom Layer w5.4: v1(2110.41,1423.67) 2144.97,1389.11 2144.97,1377.63 2195.3,1327.3 2195.3,1272.08 2194.1,1270.88 2194.1,1265.56 2054.33,1125.79 2054.33,1124.25 2043.5,1113.42 2043.5,913.5 1877,747 1700.15,747 1660.3,707.15 1660.3,456.85 1690.52,426.63 1693.51,426.63 1700.74,419.4 2238.6,419.4 J8.7@2346,312 2305.77,271.77 2305.77,195.33 2327.14,173.96 2327.14,153.86 2344,137 R84.1@2346,137
TX_ER_EMB: J13.16 R84.2 | length 2547.2
  Top Layer w5.4: v1@2396,167 2396,71 2409.6,57.4 2421.49,57.4 2426.89,62.8 2426.89,121.6 2432.29,127 2443.09,127 2448.49,121.6 2448.49,62.8 2453.89,57.4 2464.69,57.4 2470.09,62.8 2470.09,121.6 2475.49,127 2486.29,127 2491.69,121.6 2491.69,62.8 2497.09,57.4 2507.89,57.4 2513.29,62.8 2513.29,121.6 2518.69,127 2529.49,127 2534.89,121.6 2534.89,62.8 2540.29,57.4 2551.09,57.4 2556.49,62.8 2556.49,121.6 2561.89,127 2572.69,127 2578.09,121.6 2578.09,62.8 2583.49,57.4 2594.29,57.4 2599.69,62.8 2599.69,121.6 2605.09,127 2615.89,127 2621.29,121.6 2621.29,62.8 2626.69,57.4 2637.49,57.4 2642.89,62.8 2642.89,121.6 2648.29,127 2659.09,127 2664.49,121.6 2664.49,62.8 2669.89,57.4 2680.69,57.4 2686.09,62.8 2686.09,121.6 2691.49,127 2702.29,127 2707.69,121.6 2707.69,62.8 2713.09,57.4 2740,57.4 2756,73.4 2756,223 2714.37,264.63 2607.37,264.63 2599.48,272.52 2599.48,360.52 2695.86,456.9 2955.26,456.9 3028.1,529.74 3028.1,531 3062,564.9 3110,564.9 3111,563.9 3164.72,563.9 3196,595.18 v1@3196,597
  Bottom Layer w5.4: R84.2@2386,137 2386,157 v1@2396,167 ; v1@3196,597 3204.36,605.36 J13.16@3204.36,640.8
  other v1: 2398,166 3198,596
TXD0: C3.2 R66.1 U1.38 | length 175.1
  Top Layer w4.1: U1.38@2056.54,1417.8 2083.61,1417.8 2087.35,1414.06 2091.65,1414.06 2103.76,1401.95 2106.63,1401.95 2113.03,1395.55 2127.97,1395.55 ; 2127.98,1395.54 2135.47,1395.54 2145.62,1385.39 2145.62,1377.9 2161,1362.52 2161,1357 2173,1345 2184,1345 C3.2@2191,1352
TXD0_EMB: J13.42 R101.2 | length 2562.2
  Top Layer w4.1: v1@1516,492 1529.48,505.48 1539.93,505.48 1547.1,498.31 1547.1,387.6 1572.6,362.1 1607.4,362.1 1637.9,392.6 1637.9,515.4 1606.7,546.6 1453.4,546.6 1436,564 1436,652 1551,767 2323,767 2350,794 2350,894.6 2366.5,911.1 2554.5,911.1 2569.6,896 2569.6,767.1 2624.7,712 2721,712 2781,652 2794.9,652 2804.9,662 2804.9,673.1 v1@2786,692
  Bottom Layer w4.1: R101.2@1516,442 v1@1516,492 ; v1@2786,692 2795.36,682.64 J13.42@2795.36,640.8
  other v1: 1518,491 2788,691
TXD0_H: J8.23 R66.2 R101.1 | length 2174.4
  Top Layer w4.1: J8.23@1546,312 1519.42,338.58 1510.52,338.58 1497.1,352 1497.1,409.9 1476.9,430.1 1346.6,430.1 1343.1,433.6 1343.1,594.15 1542.35,793.4 2178.1,793.4 2272.1,887.4 2272.1,1227.4 2307.1,1262.4 2307.1,1321.6 2276.7,1352 R66.2@2210.3,1352
  Bottom Layer w4.1: R101.1@1516,402 1516,383.15 1511.9,379.05 1505.65,379.05 1501.55,374.95 1501.55,356.45 J8.23@1546,312
TXD1: C4.2 R68.1 U1.37 | length 175.1
  Top Layer w4.1: U1.37@2056.54,1398.12 2087.22,1398.12 2090.96,1394.38 2091.65,1394.38 2095.18,1390.85 2102.03,1390.85 2108.43,1384.45 2123.37,1384.45 ; 2123.38,1384.44 2130.87,1384.44 2134.52,1380.79 2134.52,1373.3 2149.9,1357.92 2149.9,1352.4 2168.4,1333.9 2181.64,1333.9 2191,1324.54 C4.2@2191,1322
TXD1_EMB: J13.40 R102.2 | length 2578.3
  Top Layer w4.1: v1@1476,492 1485.29,492 1536,441.29 1536,383 1568,351 1612,351 1649,388 1649,520 1611.3,557.7 1458,557.7 1447.1,568.6 1447.1,647.4 1555.6,755.9 2327.6,755.9 2361.1,789.4 2361.1,890 2371.1,900 2549.9,900 2558.5,891.4 2558.5,762.5 2619.74,701.26 2620.62,700.9 2716.4,700.9 2776.4,640.9 2799.5,640.9 2816,657.4 2816,683.02 v1@2824.47,691.49
  Bottom Layer w4.1: R102.2@1476,442 v1@1476,492 ; v1@2824.47,691.49 2831,684.96 2831,668 2827.36,664.36 J13.40@2827.36,640.8
  other v1: 1478,491 2826.47,690.49
TXD1_H: J8.25 R68.2 R102.1 | length 2154.3
  Top Layer w4.1: J8.25@1446,312 1486,352 1486,405 1472,419 1342,419 1332,429 1332,598.75 1537.75,804.5 2173.5,804.5 2261,892 2261,1232 2296,1267 2296,1317 2272.95,1340.05 2227.85,1340.05 2210.3,1322.5 R68.2@2210.3,1322
  Bottom Layer w4.1: J8.25@1446,312 1490.45,356.45 1490.45,374.95 1486.35,379.05 1480.1,379.05 1476,383.15 R102.1@1476,402
TXD2: J8.21 R99.1 U1.36 | length 2323.4
  Top Layer w5.4: U1.36@2056.54,1378.44 2097.82,1378.44 2103.57,1372.69 2118.51,1372.69 2131,1360.2 2131,1342 v1@2161,1312
  Bottom Layer w5.4: R99.1@1601,142 1601,161.7 1591.7,171 1499,171 1489,181 1489,247 1499,257 1636,257 1646,267 J8.21@1646,312 1573.5,384.5 1573.5,510 1563.5,520 1421.03,520 1411.03,530 1411.03,761.41 1698.62,1049 1868,1049 1911.7,1092.7 1911.7,1173.42 1921.7,1183.42 1921.7,1268.42 2028.28,1375 2109.46,1375 2124.86,1359.6 2125.86,1359.6 2147.06,1338.4 2147.06,1325.94 v1@2161,1312
  other v1: 2163,1311
TXD2_EMB: J13.38 R99.2 | length 2543.9
  Top Layer w5.4: v1@1691,182 1691,54 1700,45 3059,45 3069,55 3069,99 3059,109 2814,109 2779,144 2779,249 2695,333 v1(2695,354)
  Bottom Layer w5.4: R99.2@1641,142 1641,161.7 1646.3,167 1676,167 v1@1691,182 ; v1(2695,354) 2744.44,403.44 2744.44,500.44 2826,582 2858.36,614.36 J13.38@2858.36,640.8
  other v1: 1693,181 2828,581
TXD3: J8.19 R83.1 U1.35 | length 2333.8
  Top Layer w5.4: U1.35@2056.54,1358.76 2109.24,1358.76 2116,1352 2116,1327 v1@2128.5,1314.5
  Bottom Layer w5.4: R83.1@1731,142 1733,142 1762.67,171.67 1762.67,171.77 1786.23,195.33 1786.23,271.77 J8.19@1746,312 1702.9,312 1662.67,352.23 1650.77,352.23 1585.9,417.1 1585.9,515.14 1568.64,532.4 1563.63,532.4 1558.23,537.8 1558.23,573.6 1552.83,579 1542.03,579 1536.63,573.6 1536.63,537.8 1531.23,532.4 1520.43,532.4 1515.03,537.8 1515.03,573.6 1509.63,579 1498.83,579 1493.43,573.6 1493.43,537.8 1488.03,532.4 1477.23,532.4 1471.83,537.8 1471.83,573.6 1466.43,579 1455.63,579 1450.23,573.6 1450.23,537.8 1444.83,532.4 1433.43,532.4 1423.43,542.4 1423.43,756.27 1703.76,1036.6 1873.14,1036.6 1924.1,1087.56 1924.1,1168.28 1934.1,1178.28 1934.1,1263.28 2033.42,1362.6 2104.32,1362.6 2128.5,1338.42 v1@2128.5,1314.5
  other v1: 2130.5,1313.5
TXD3_EMB: J13.36 R83.2 | length 2549.4
  Top Layer w5.4: v1@1691,282 1691,374.23 1731,414.23 1956.23,414.23 1993,451 1993,707 2012,726 2128,726 2154,700 2154,650.43 2148.6,645.03 2113.4,645.03 2108,639.63 2108,628.83 2113.4,623.43 2148.6,623.43 2154,618.03 2154,607.23 2148.6,601.83 2113.4,601.83 2108,596.43 2108,585.63 2113.4,580.23 2148.6,580.23 2154,574.83 2154,564.03 2148.6,558.63 2113.4,558.63 2108,553.23 2108,542.43 2113.4,537.03 2148.6,537.03 2154,531.63 2154,520.83 2148.6,515.43 2113.4,515.43 2108,510.03 2108,499.23 2113.4,493.83 2148.6,493.83 2154,488.43 2154,477.63 2148.6,472.23 2113.4,472.23 2108,466.83 2108,456.03 2113.4,450.63 2148.6,450.63 2185,414.23 2466,414.23 2603.77,552 v1(2861,552)
  Bottom Layer w5.4: R83.2@1691,142 1693,142 1709.86,158.86 1709.86,171.58 1711.7,173.42 1711.7,190.58 1691,211.28 v1@1691,282 ; v1(2861,552) 2890.36,581.36 J13.36@2890.36,640.8
  other v1: 1693,281
TXD4: J8.17 R76.1 U1.34 | length 2324.3
  Top Layer w5.4: U1.34@2056.54,1339.08 2097.6,1339.08 2103.6,1333.08 v1@2103.6,1282
  Bottom Layer w5.4: 1700.76,352.22 1680.22,352.22 1667.81,364.63 1658.37,364.63 1598.3,424.7 1598.3,523 1577,544.3 1577,578 1563,592 1536,592 1530.6,597.4 1530.6,663.6 1525.2,669 1514.4,669 1509,663.6 1509,597.4 1503.6,592 1492.8,592 1487.4,597.4 1487.4,663.6 1482,669 1471.2,669 1465.8,663.6 1465.8,597.4 1460.4,592 1449,592 1435.83,605.17 1435.83,751.13 1708.9,1024.2 1878.28,1024.2 1936.5,1082.42 1936.5,1163.14 1946.5,1173.14 1946.5,1229.32 2027.34,1310.16 2075.44,1310.16 v1@2103.6,1282 ; 1700.77,352.23 1805.77,352.23 J8.17@1846,312 1805.77,271.77 1805.77,191.77 1786,172 R76.1@1786,142
  other v1: 2105.6,1281
TXD4_EMB: J13.34 R76.2 | length 2554.4
  Top Layer w5.4: v1@1866,142 1836.23,171.77 1821.23,171.77 1801,192 1801,356.83 1846,401.83 1961.37,401.83 2010.8,451.26 2050.6,451.26 2056,456.66 2056,467.46 2050.6,472.86 2010.8,472.86 2005.4,478.26 2005.4,489.06 2010.8,494.46 2050.6,494.46 2056,499.86 2056,510.66 2050.6,516.06 2010.8,516.06 2005.4,521.46 2005.4,532.26 2010.8,537.66 2050.6,537.66 2056,543.06 2056,553.86 2050.6,559.26 2010.8,559.26 2005.4,564.66 2005.4,575.46 2010.8,580.86 2050.6,580.86 2056,586.26 2056,597.06 2050.6,602.46 2010.8,602.46 2005.4,607.86 2005.4,618.66 2010.8,624.06 2050.6,624.06 2056,629.46 2056,640.26 2050.6,645.66 2010.8,645.66 2005.4,651.06 2005.4,693.4 2025.6,713.6 2076.4,713.6 2095.6,694.4 2095.6,450.89 2108.26,438.23 2143.46,438.23 2179.86,401.83 2471.14,401.83 2600.61,531.3 2869.58,531.3 2890.28,552 v1@2896,552
  Bottom Layer w5.4: R76.2@1826,142 v1@1866,142 ; v1@2896,552 2921.36,577.36 J13.34@2921.36,640.8
  other v1: 1868,141 2898,551
TXD5: J8.15 R85.1 U1.33 | length 2324.9
  Top Layer w5.4: v1@2048.54,1289.46 2056.54,1297.46 U1.33@2056.54,1319.4
  Bottom Layer w5.4: R85.1@1926,142 1924,142 1896,170 1896,262 J8.15@1946,312 1893.37,364.63 1685.35,364.63 1672.95,377.03 1665.97,377.03 1610.7,432.3 1610.7,528.14 1591,547.84 1591,581.54 1547,625.54 1547,674 1538,683 1460,683 1448.23,694.77 1448.23,745.99 1714.04,1011.8 1725.44,1011.8 1730.84,1006.4 1730.84,918.4 1736.24,913 1747.04,913 1752.44,918.4 1752.44,1006.4 1757.84,1011.8 1768.64,1011.8 1774.04,1006.4 1774.04,918.4 1779.44,913 1790.24,913 1795.64,918.4 1795.64,1006.4 1801.04,1011.8 1883.42,1011.8 1948.9,1077.28 1948.9,1158 1958.9,1168 1958.9,1224.18 2024.18,1289.46 v1@2048.54,1289.46
  other v1: 2050.54,1288.46
TXD5_EMB: J13.32 R85.2 | length 2550.5
  Top Layer w5.4: v1@1984.86,170.86 1984.86,151.16 1983,149.3 1983,77 1963.4,57.4 1928.6,57.4 1923.2,62.8 1923.2,84.6 1917.8,90 1907,90 1901.6,84.6 1901.6,62.8 1896.2,57.4 1885.4,57.4 1880,62.8 1880,84.6 1874.6,90 1863.8,90 1858.4,84.6 1858.4,62.8 1853,57.4 1842.2,57.4 1836.8,62.8 1836.8,84.6 1831.4,90 1820.6,90 1815.2,84.6 1815.2,62.8 1809.8,57.4 1799,57.4 1793.6,62.8 1793.6,84.6 1788.2,90 1777.4,90 1772,84.6 1772,62.8 1766.6,57.4 1755.8,57.4 1750.4,62.8 1750.4,84.6 1745,90 1734.2,90 1728.8,84.6 1728.8,62.8 1723.4,57.4 1712,57.4 1703.4,66 1703.4,107.4 1717.4,121.4 1717.4,160.6 1722.8,166 1733.6,166 1739,160.6 1739,121.4 1744.4,116 1755.2,116 1760.6,121.4 1760.6,160.6 1766,166 1776.8,166 1782.2,160.6 1782.2,121.4 1787.6,116 1875,116 1905.77,146.77 1905.77,367.82 1927.38,389.43 2476.28,389.43 2605.75,518.9 2912.62,518.9 v1(2953.36,559.64)
  Bottom Layer w5.4: R85.2@1966,142 1968,142 1984.86,158.86 v1@1984.86,170.86 ; v1(2953.36,559.64) J13.32@2953.36,640.8
  other v1: 1986.86,169.86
